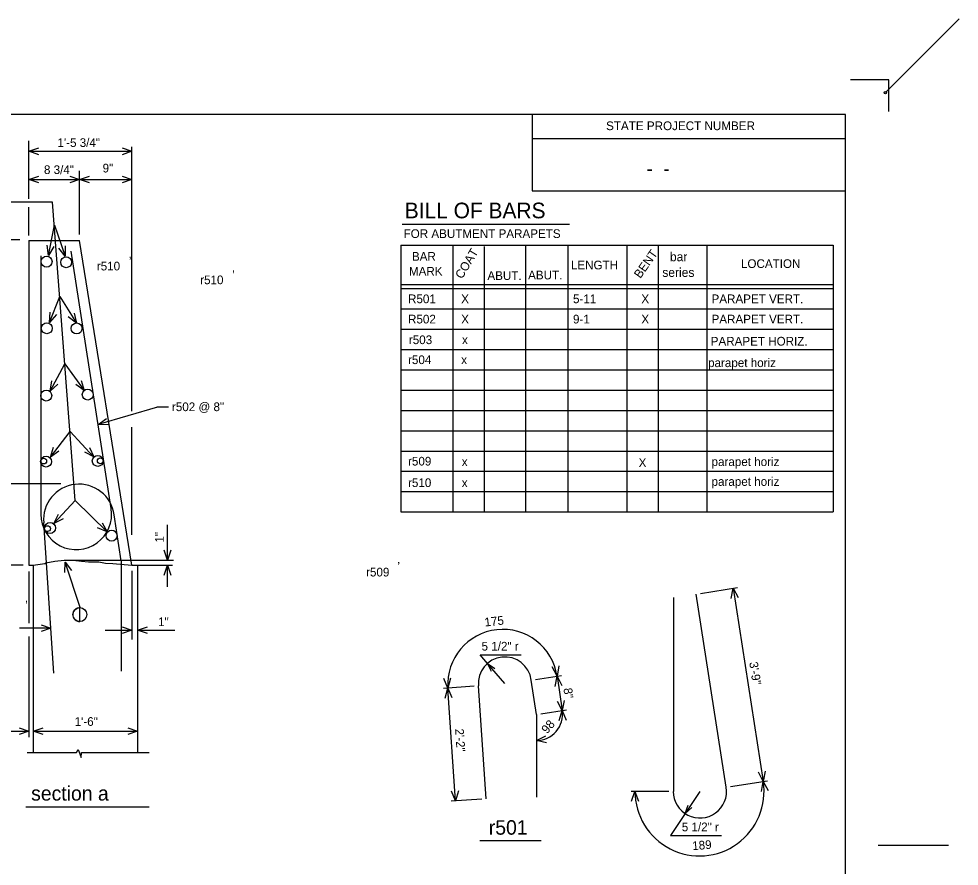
# Model space of a CAD drawing. Extents: x -81 to -44.8, y 85.9 to 111.1.
# Drawn here: x -58.31 to -44.79, y 98.39 to 110.57 of the extents above; entities that cross this region are included whole.
import ezdxf

# ---------------------------------------------------------------- set-up
doc = ezdxf.new("R2010")
doc.units = 0
for name, color, linetype in [('Default', 7, 'Continuous'), ('Level 1', 7, 'Continuous'), ('Level 16', 7, 'Continuous'), ('Level 2', 7, 'Continuous'), ('Level 37', 7, 'Continuous'), ('Level 49', 7, 'Continuous'), ('Level 9', 7, 'Continuous')]:
    doc.layers.add(name, color=color, linetype=linetype)

msp = doc.modelspace()

# ---------------------------------------------------------------- linework, layer by layer
at = {"layer": 'Default'}
for p, q in [((-58.16, 107.979), (-58.16, 108.812)), ((-56.681, 108.197), (-56.681, 108.726)), ((-58.16, 108.664), (-56.681, 108.664)), ((-57.819, 107.932), (-58.544, 107.932)), ((-57.495, 103.644), (-57.819, 107.932)), ((-57.88, 107.168), (-57.794, 107.602)), ((-57.794, 107.602), (-57.64, 107.157)), ((-58.16, 107.382), (-57.431, 107.382)), ((-58.16, 107.382), (-58.16, 102.716)), ((-56.681, 102.716), (-57.431, 107.382)), ((-56.977, 103.53), (-57.555, 107.231)), ((-57.991, 107.164), (-57.991, 103.45)), ((-57.862, 106.204), (-57.716, 106.577)), ((-57.716, 106.577), (-57.478, 106.193)), ((-57.855, 105.219), (-57.643, 105.611)), ((-57.643, 105.611), (-57.365, 105.228)), ((-56.314, 104.987), (-57.166, 104.738)), ((-57.85, 104.267), (-57.569, 104.635)), ((-57.569, 104.635), (-57.231, 104.271)), ((-56.681, 103.151), (-56.681, 104.701)), ((-57.801, 103.315), (-57.495, 103.644)), ((-57.495, 103.644), (-57.036, 103.195)), ((-56.835, 102.777), (-56.934, 103.438)), ((-57.801, 101.164), (-57.948, 103.324)), ((-56.167, 102.789), (-56.167, 103.298)), ((-57.418, 102.093), (-57.64, 102.759)), ((-57.616, 102.789), (-56.084, 102.789)), ((-56.835, 102.777), (-56.835, 101.195)), ((-58.16, 102.716), (-58.097, 102.716)), ((-58.097, 102.716), (-58.097, 100.017)), ((-56.681, 102.716), (-56.098, 102.716)), ((-56.681, 102.716), (-56.597, 102.716)), ((-56.681, 102.636), (-56.681, 101.646)), ((-56.597, 102.716), (-56.597, 100.017)), ((-56.167, 102.407), (-56.167, 102.716)), ((-57.845, 101.812), (-58.296, 101.812)), ((-57.065, 101.783), (-56.681, 101.783)), ((-56.597, 101.783), (-56.064, 101.783)), ((-58.204, 99.242), (-56.431, 99.242))]:
    msp.add_line(p, q, dxfattribs=at)
msp.add_lwpolyline([(-58.097, 102.716), (-57.932, 102.738), (-57.919, 102.75), (-57.787, 102.772), (-57.652, 102.79), (-57.524, 102.787), (-57.404, 102.775), (-57.303, 102.766), (-57.155, 102.762), (-57.057, 102.747), (-56.956, 102.738), (-56.681, 102.716)], dxfattribs=at)
for centre, radius in [((-57.906, 107.078), 0.0788), ((-57.625, 107.07), 0.0788), ((-57.903, 106.121), 0.0788), ((-57.475, 106.118), 0.0788), ((-57.911, 105.154), 0.0788), ((-57.314, 105.168), 0.0788), ((-57.913, 104.205), 0.0788), ((-57.948, 104.212), 0.0417), ((-57.17, 104.215), 0.0788), ((-57.134, 104.216), 0.0417), ((-57.857, 103.251), 0.0788), ((-57.894, 103.241), 0.0417), ((-56.972, 103.14), 0.0788)]:
    msp.add_circle(centre, radius, dxfattribs=at)
for centre, start, end in [((-57.44, 103.37), 7.615, 185.2003), ((-57.481, 103.45), 180, 9)]:
    msp.add_arc(centre, 0.51, start, end, dxfattribs=at)
at = {"layer": 'Level 1'}
for p, q in [((-45.797, 109.692), (-46.351, 109.692)), ((-45.797, 109.237), (-45.797, 109.692)), ((-46.422, 109.192), (-77.797, 109.192)), ((-50.928, 109.191), (-50.928, 108.096)), ((-46.422, 88.192), (-46.422, 109.192)), ((-50.928, 108.847), (-46.422, 108.847)), ((-57.431, 107.466), (-57.431, 108.385)), ((-58.16, 108.257), (-57.431, 108.257)), ((-57.431, 108.257), (-56.681, 108.257)), ((-56.681, 104.928), (-56.681, 108.273)), ((-50.928, 108.096), (-46.422, 108.096)), ((-58.16, 107.456), (-58.16, 107.861)), ((-58.289, 107.393), (-58.878, 107.393)), ((-56.153, 104.987), (-56.319, 104.987)), ((-57.703, 103.885), (-58.479, 103.885)), ((-58.243, 102.716), (-58.878, 102.716)), ((-58.16, 102.624), (-58.16, 101.884)), ((-48.508, 102.311), (-47.974, 102.394)), ((-48.036, 102.385), (-47.603, 99.609)), ((-48.896, 102.251), (-48.896, 99.466)), ((-48.136, 99.526), (-48.57, 102.301)), ((-58.16, 101.692), (-58.16, 100.244)), ((-51.318, 101.015), (-51.569, 101.304)), ((-50.876, 101.075), (-50.505, 101.131)), ((-50.567, 101.121), (-50.493, 100.626)), ((-50.864, 100.571), (-50.938, 101.066)), ((-51.761, 100.976), (-52.199, 100.946)), ((-52.026, 99.33), (-52.137, 100.951)), ((-51.588, 99.36), (-51.699, 100.98)), ((-50.802, 100.58), (-50.431, 100.636)), ((-50.864, 100.571), (-50.864, 99.384)), ((-58.743, 100.332), (-58.16, 100.332)), ((-58.097, 100.332), (-56.597, 100.332)), ((-48.075, 99.535), (-47.541, 99.619)), ((-48.959, 99.466), (-49.504, 99.466)), ((-48.514, 99.466), (-48.727, 99.148)), ((-51.65, 99.356), (-52.088, 99.326)), ((-51.677, 98.759), (-50.798, 98.759))]:
    msp.add_line(p, q, dxfattribs=at)
for points in [[(-48.063, 102.238), (-48.036, 102.385), (-47.966, 102.253)], [(-51.569, 101.304), (-51.675, 101.426), (-51.084, 101.426)], [(-51.51, 101.189), (-51.569, 101.304), (-51.463, 101.23)], [(-50.54, 101.268), (-50.567, 101.121), (-50.636, 101.254)], [(-50.595, 100.975), (-50.567, 101.121), (-50.498, 100.989)], [(-52.098, 101.094), (-52.137, 100.951), (-52.195, 101.088)], [(-52.176, 100.807), (-52.137, 100.951), (-52.079, 100.813)], [(-50.466, 100.773), (-50.493, 100.626), (-50.562, 100.758)], [(-50.536, 100.484), (-50.493, 100.626), (-50.439, 100.487)], [(-50.718, 100.165), (-50.864, 100.196), (-50.73, 100.262)], [(-47.576, 99.756), (-47.603, 99.609), (-47.672, 99.741)], [(-47.629, 99.462), (-47.603, 99.609), (-47.533, 99.477)], [(-51.987, 99.474), (-52.026, 99.33), (-52.084, 99.468)], [(-49.496, 99.325), (-49.448, 99.466), (-49.399, 99.325)], [(-48.632, 99.234), (-48.727, 99.148), (-48.684, 99.269)], [(-48.727, 99.148), (-48.938, 98.832), (-48.203, 98.832)]]:
    msp.add_lwpolyline(points, dxfattribs=at)
for centre, radius, start, end in [((-51.349, 101.004), 0.79, 8.5231, 183.9058), ((-51.318, 101.015), 0.383, 7.615, 185.2003), ((-50.864, 100.571), 0.375, 270, 8.5231), ((-48.52, 99.466), 0.928, 180, 8.8807), ((-48.514, 99.466), 0.383, 180, 9)]:
    msp.add_arc(centre, radius, start, end, dxfattribs=at)
at = {"layer": 'Level 2'}
for p, q in [((-45.848, 109.507), (-44.787, 110.568)), ((-52.796, 107.618), (-50.388, 107.618)), ((-52.815, 107.315), (-51.59, 107.315)), ((-52.815, 107.315), (-52.815, 103.481)), ((-52.065, 107.315), (-52.065, 103.481)), ((-51.615, 107.298), (-51.615, 103.481)), ((-51.59, 107.315), (-50.456, 107.315)), ((-51.022, 107.315), (-51.022, 103.481)), ((-50.456, 107.315), (-48.415, 107.315)), ((-50.415, 107.315), (-50.415, 103.481)), ((-49.565, 107.315), (-49.565, 103.481)), ((-49.115, 107.315), (-49.115, 103.481)), ((-48.415, 107.315), (-46.598, 107.315)), ((-48.415, 107.315), (-48.415, 103.481)), ((-46.598, 107.315), (-46.598, 103.481)), ((-52.815, 106.752), (-50.456, 106.752)), ((-52.815, 106.69), (-50.456, 106.69)), ((-50.456, 106.752), (-48.415, 106.752)), ((-50.456, 106.69), (-48.415, 106.69)), ((-48.415, 106.752), (-46.598, 106.752)), ((-48.415, 106.69), (-46.598, 106.69)), ((-52.815, 106.398), (-50.456, 106.398)), ((-50.456, 106.398), (-48.415, 106.398)), ((-48.415, 106.398), (-46.598, 106.398)), ((-52.815, 106.106), (-50.456, 106.106)), ((-50.456, 106.106), (-48.415, 106.106)), ((-48.415, 106.106), (-46.598, 106.106)), ((-52.815, 105.815), (-50.456, 105.815)), ((-50.456, 105.815), (-48.415, 105.815)), ((-48.415, 105.815), (-46.598, 105.815)), ((-52.815, 105.523), (-50.456, 105.523)), ((-50.456, 105.523), (-48.415, 105.523)), ((-48.415, 105.523), (-46.598, 105.523)), ((-52.815, 105.231), (-50.456, 105.231)), ((-50.456, 105.231), (-48.415, 105.231)), ((-48.415, 105.231), (-46.598, 105.231)), ((-52.815, 104.94), (-50.456, 104.94)), ((-50.456, 104.94), (-48.415, 104.94)), ((-48.415, 104.94), (-46.598, 104.94)), ((-52.815, 104.648), (-50.456, 104.648)), ((-50.456, 104.648), (-48.415, 104.648)), ((-48.415, 104.648), (-46.598, 104.648)), ((-52.815, 104.356), (-50.456, 104.356)), ((-50.456, 104.356), (-48.415, 104.356)), ((-48.415, 104.356), (-46.598, 104.356)), ((-52.815, 104.065), (-50.456, 104.065)), ((-50.456, 104.065), (-48.415, 104.065)), ((-48.415, 104.065), (-46.598, 104.065)), ((-52.815, 103.773), (-50.456, 103.773)), ((-50.456, 103.773), (-48.415, 103.773)), ((-48.415, 103.773), (-46.598, 103.773)), ((-52.815, 103.481), (-46.598, 103.481)), ((-52.815, 103.481), (-46.598, 103.481)), ((-57.426, 101.904), (-57.426, 102.105))]:
    msp.add_line(p, q, dxfattribs=at)
for points in [[(-58.019, 108.615), (-58.16, 108.664), (-58.019, 108.713)], [(-56.822, 108.713), (-56.681, 108.664), (-56.822, 108.615)], [(-58.019, 108.209), (-58.16, 108.257), (-58.019, 108.306)], [(-57.572, 108.306), (-57.431, 108.257), (-57.572, 108.209)], [(-57.29, 108.209), (-57.431, 108.257), (-57.29, 108.306)], [(-56.822, 108.306), (-56.681, 108.257), (-56.822, 108.209)], [(-57.804, 107.297), (-57.88, 107.168), (-57.9, 107.316)], [(-57.64, 107.306), (-57.64, 107.157), (-57.732, 107.274)], [(-57.765, 106.317), (-57.862, 106.204), (-57.856, 106.353)], [(-57.511, 106.338), (-57.478, 106.193), (-57.594, 106.287)], [(-57.743, 105.319), (-57.855, 105.219), (-57.829, 105.366)], [(-57.408, 105.371), (-57.365, 105.228), (-57.487, 105.313)], [(-57.017, 104.731), (-57.166, 104.738), (-57.044, 104.824)], [(-57.729, 104.354), (-57.85, 104.267), (-57.809, 104.41)], [(-57.287, 104.407), (-57.226, 104.271), (-57.358, 104.341)], [(-57.667, 103.38), (-57.801, 103.315), (-57.736, 103.449)], [(-57.108, 103.326), (-57.036, 103.195), (-57.173, 103.254)], [(-56.118, 102.93), (-56.167, 102.789), (-56.215, 102.93)], [(-57.642, 102.61), (-57.64, 102.759), (-57.549, 102.64)], [(-56.215, 102.575), (-56.167, 102.716), (-56.118, 102.575)], [(-57.985, 101.861), (-57.845, 101.812), (-57.985, 101.764)], [(-56.822, 101.831), (-56.681, 101.783), (-56.822, 101.734)], [(-56.457, 101.734), (-56.597, 101.783), (-56.457, 101.831)], [(-58.301, 100.38), (-58.16, 100.332), (-58.301, 100.283)], [(-57.957, 100.283), (-58.097, 100.332), (-57.957, 100.38)], [(-56.738, 100.38), (-56.597, 100.332), (-56.738, 100.283)], [(-58.186, 100.023), (-57.474, 100.023), (-57.452, 100.065), (-57.411, 99.952), (-57.405, 100.023), (-56.431, 100.023)]]:
    msp.add_lwpolyline(points, dxfattribs=at)
msp.add_lwpolyline([(-57.426, 101.905), (-57.426, 102.105), (-57.426, 102.105), (-57.445, 102.104), (-57.467, 102.099), (-57.486, 102.088), (-57.504, 102.072), (-57.516, 102.056), (-57.525, 102.035), (-57.529, 102.01), (-57.527, 101.986), (-57.523, 101.969), (-57.509, 101.945), (-57.496, 101.932), (-57.48, 101.919), (-57.463, 101.912), (-57.448, 101.907), (-57.44, 101.906)], close=True, dxfattribs=at)
msp.add_circle((-57.428, 102.006), 0.1, dxfattribs=at)
at = {"layer": 'Level 37'}
msp.add_line((-45.952, 98.692), (-44.941, 98.692), dxfattribs=at)
at = {"layer": 'Level 49'}
msp.add_circle((-45.848, 109.507), 0.0152, dxfattribs=at)

# ---------------------------------------------------------------- texts
at = {"layer": 'Default'}
for s, height, p in [('1\'-5 3/4"', 0.125, (-57.75, 108.726)), ('1"', 0.125, (-56.303, 101.84)), ('section a', 0.2083, (-58.128, 99.333))]:
    msp.add_text(s, height=height, dxfattribs=at).set_placement(p)
msp.add_text('1"', height=0.125, rotation=90, dxfattribs=at).set_placement((-56.221, 103.041))
at = {"layer": 'Level 1'}
for s, height, p in [('STATE PROJECT NUMBER', 0.12525, (-49.863, 108.968)), ('8 3/4"', 0.125, (-57.944, 108.337)), ('9"', 0.125, (-57.101, 108.36)), ('    -  -  ', 0.2023, (-49.581, 108.315)), ('r502 @ 8"', 0.125, (-56.104, 104.93)), ('5 1/2" r', 0.125, (-51.653, 101.489)), ('1\'-6"', 0.125, (-57.503, 100.407)), ('r501', 0.2083, (-51.549, 98.843)), ('5 1/2" r', 0.125, (-48.775, 98.892))]:
    msp.add_text(s, height=height, dxfattribs=at).set_placement(p)
for s, rotation, p in [('175', 6.2145, (-51.604, 101.834)), ('3\'-9"', 278.8807, (-47.806, 101.318)), ('8"', 278.5231, (-50.477, 100.943)), ('98', 49.2616, (-50.711, 100.285)), ('2\'-2"', 273.9058, (-52.034, 100.363)), ('189', 4.4403, (-48.62, 98.62))]:
    msp.add_text(s, height=0.125, rotation=rotation, dxfattribs=at).set_placement(p)
at = {"layer": 'Level 16'}
for s, p in [('r504 ', (-52.71, 105.606)), ('x', (-51.946, 105.606)), ('parapet horiz', (-48.397, 105.563))]:
    msp.add_text(s, height=0.125, dxfattribs=at).set_placement(p)
at = {"layer": 'Level 2'}
for s, height, p in [('BILL OF BARS', 0.225, (-52.757, 107.701)), ('FOR ABUTMENT PARAPETS', 0.125, (-52.774, 107.418)), ('BAR', 0.125, (-52.654, 107.091)), ('bar', 0.1294, (-48.945, 107.084)), ('LENGTH', 0.125, (-50.369, 106.967)), ('LOCATION', 0.125, (-47.924, 106.987)), ('MARK', 0.125, (-52.697, 106.877)), ('ABUT.', 0.125, (-51.569, 106.815)), ('ABUT.', 0.125, (-50.984, 106.823)), ('series', 0.1294, (-49.055, 106.859)), ('R501', 0.125, (-52.71, 106.481)), ('X', 0.125, (-51.946, 106.481)), (' 5-11', 0.125, (-50.385, 106.481)), ('X', 0.125, (-49.356, 106.481)), ('PARAPET VERT.   ', 0.125, (-48.347, 106.481)), ('R502', 0.125, (-52.71, 106.19)), ('X', 0.125, (-51.946, 106.19)), (' 9-1 ', 0.125, (-50.385, 106.19)), ('X', 0.125, (-49.356, 106.19)), ('PARAPET VERT.   ', 0.125, (-48.347, 106.19)), ('r503', 0.125, (-52.698, 105.893)), ('x', 0.125, (-51.934, 105.893)), ('PARAPET HORIZ.  ', 0.125, (-48.359, 105.872))]:
    msp.add_text(s, height=height, dxfattribs=at).set_placement(p)
for s, rotation, p in [('COAT', 59.0083, (-51.934, 106.82)), ('BENT', 54.9994, (-49.37, 106.828))]:
    msp.add_text(s, height=0.125, rotation=rotation, dxfattribs=at).set_placement(p)
at = {"layer": 'Level 9'}
for s, p in [('r510', (-57.184, 106.952)), (',', (-56.728, 107.13)), (',', (-55.242, 106.932)), ('r510', (-55.698, 106.754)), ('r509 ', (-52.71, 104.148)), ('x', (-51.938, 104.141)), ('X', (-49.395, 104.127)), ('parapet horiz', (-48.347, 104.141)), ('r510 ', (-52.71, 103.839)), ('parapet horiz', (-48.347, 103.856)), ('x', (-51.938, 103.839)), (',', (-52.868, 102.742)), ('r509', (-53.313, 102.554)), (',', (-58.218, 102.186))]:
    msp.add_text(s, height=0.125, dxfattribs=at).set_placement(p)

doc.saveas('drawing.dxf')
